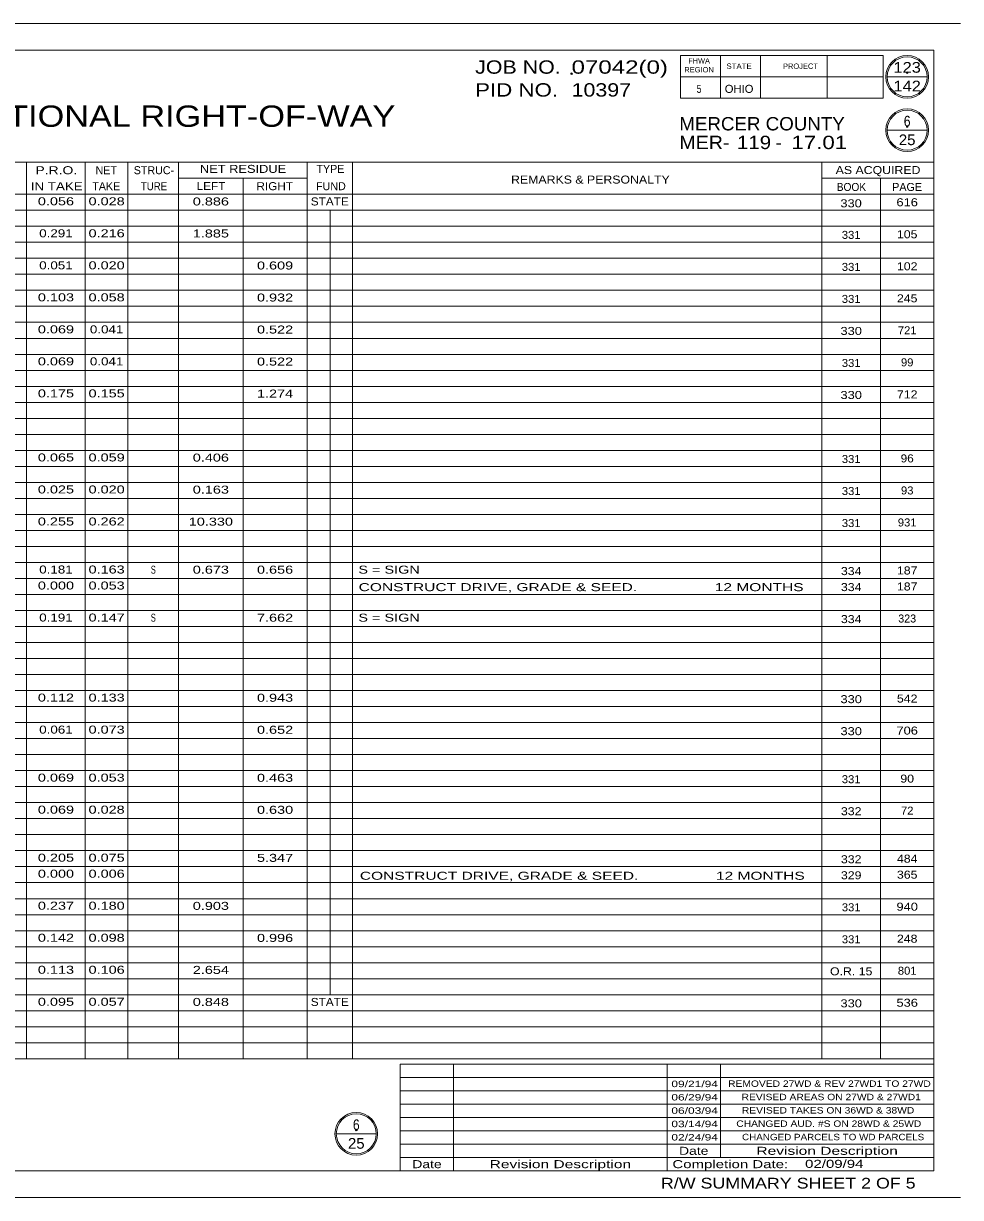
# Model space of a CAD drawing. Extents: x -1 to 34.5, y 0 to 22.
# Drawn here: x 16.94 to 34.5, y 0 to 22 of the extents above; entities that cross this region are included whole.
import ezdxf
from ezdxf.enums import TextEntityAlignment as Align

# ---------------------------------------------------------------- set-up
doc = ezdxf.new("R2010")
doc.units = 0
doc.header["$LTSCALE"] = 0.06
doc.header["$PDMODE"] = 32
doc.header["$PDSIZE"] = 0.03
doc.layers.add('1', color=7, linetype='Continuous', lineweight=13)

msp = doc.modelspace()

# ---------------------------------------------------------------- linework, layer by layer
at = {"layer": '1'}
for p, q in [((-1, 22), (34.5, 22)), ((0.5, 21.5), (34, 21.5)), ((30, 21.4), (30, 20.6)), ((30.75, 21.4), (30.75, 20.6)), ((32.002, 21.4), (32.002, 20.6)), ((29.25, 21), (33.05, 21)), ((33.125, 21), (33.875, 21)), ((33.125, 20.00258), (33.875, 20.00258)), ((0.5, 19.4), (34, 19.4)), ((16.99617, 2.6), (16.99617, 19.4)), ((18.09617, 2.6), (18.09617, 19.4)), ((18.89617, 2.6), (18.89617, 19.4)), ((19.84617, 2.6), (19.84617, 19.4)), ((22.253, 2.6), (22.253, 19.4)), ((23.103, 2.6), (23.103, 19.4)), ((31.90092, 2.6), (31.90092, 19.4)), ((19.853, 19.1), (22.253, 19.1)), ((21.053, 2.6), (21.053, 19.1)), ((31.90092, 19.1), (34, 19.1)), ((33.00092, 2.6), (33.00092, 19.1)), ((0.5, 18.8), (34, 18.8)), ((0.5, 18.5), (34, 18.5)), ((22.68783, 18.50225), (22.68783, 3.8)), ((0.5, 18.2), (34, 18.2)), ((0.5, 17.9), (34, 17.9)), ((0.5, 17.6), (34, 17.6)), ((0.5, 17.3), (34, 17.3)), ((0.5, 17), (34, 17)), ((0.5, 16.7), (34, 16.7)), ((0.5, 16.4), (34, 16.4)), ((0.5, 16.1), (34, 16.1)), ((0.5, 15.8), (34, 15.8)), ((0.5, 15.5), (34, 15.5)), ((0.5, 15.2), (34, 15.2)), ((0.5, 14.9), (34, 14.9)), ((0.5, 14.6), (34, 14.6)), ((0.5, 14.3), (34, 14.3)), ((0.5, 14), (34, 14)), ((0.5, 13.7), (34, 13.7)), ((0.5, 13.4), (34, 13.4)), ((0.5, 13.1), (34, 13.1)), ((0.5, 12.8), (34, 12.8)), ((0.5, 12.5), (34, 12.5)), ((0.5, 12.2), (34, 12.2)), ((0.5, 11.9), (34, 11.9)), ((0.5, 11.6), (34, 11.6)), ((0.5, 11.3), (34, 11.3)), ((0.5, 11), (34, 11)), ((0.5, 10.7), (34, 10.7)), ((0.5, 10.4), (34, 10.4)), ((0.5, 10.1), (34, 10.1)), ((0.5, 9.8), (34, 9.8)), ((0.5, 9.5), (34, 9.5)), ((0.5, 9.2), (34, 9.2)), ((0.5, 8.9), (34, 8.9)), ((0.5, 8.6), (34, 8.6)), ((0.5, 8.3), (34, 8.3)), ((0.5, 8), (34, 8)), ((0.5, 7.7), (34, 7.7)), ((0.5, 7.4), (34, 7.4)), ((0.5, 7.1), (34, 7.1)), ((0.5, 6.8), (34, 6.8)), ((0.5, 6.5), (34, 6.5)), ((0.5, 6.2), (34, 6.2)), ((0.5, 5.9), (34, 5.9)), ((0.5, 5.6), (34, 5.6)), ((0.5, 5.3), (34, 5.3)), ((0.5, 5), (34, 5)), ((0.5, 4.7), (34, 4.7)), ((0.5, 4.4), (34, 4.4)), ((0.5, 4.1), (34, 4.1)), ((0.5, 3.8), (34, 3.8)), ((0.5, 3.5), (34, 3.5)), ((0.5, 3.2), (34, 3.2)), ((0.5, 2.9), (34, 2.9)), ((0.5, 2.6), (34, 2.6)), ((34, 2.5), (24, 2.5)), ((24, 2.5), (24, 0.5)), ((25, 2.5), (25, 0.5)), ((29, 2.5), (29, 0.5)), ((30, 2.5), (30, 0.75)), ((34, 2.25), (24, 2.25)), ((34, 2), (24, 2)), ((34, 1.75), (24, 1.75)), ((34, 1.5), (24, 1.5)), ((22.80008, 1.1965), (23.55008, 1.1965)), ((34, 1.25), (24, 1.25)), ((34, 1), (24, 1)), ((34, 0.75), (24, 0.75)), ((-1, 0), (34.5, 0))]:
    msp.add_line(p, q, dxfattribs=at)
msp.add_lwpolyline([(34, 21.5), (34, 0.5), (0.5, 0.5)], dxfattribs=at)
msp.add_lwpolyline([(29.25, 20.6), (33.05, 20.6), (33.05, 21.4), (29.25, 21.4)], close=True, dxfattribs=at)
for centre, radius in [((33.5, 21), 0.4), ((33.5, 21), 0.375), ((33.5, 20), 0.4), ((33.5, 20), 0.375), ((23.17506, 1.19392), 0.4), ((23.17506, 1.19392), 0.375)]:
    msp.add_circle(centre, radius, dxfattribs=at)
for p in [(27.21, 21.05892), (33.5, 21.07758), (33.5, 20.07), (23.17508, 1.26392)]:
    msp.add_point(p, dxfattribs=at)

# ---------------------------------------------------------------- texts
for s, height, width, p in [('FHWA', 0.1, 0.95, (29.60004, 21.25)), ('REGION', 0.1, 1.05, (29.6, 21.08333)), ('STATE', 0.1, 1.1, (30.35, 21.15)), ('PROJECT', 0.1, 1.05, (31.50004, 21.15)), ('123', 0.2, 1.15, (33.5, 21.07758)), ('142', 0.2, 1.15, (33.5, 20.72758)), ('5', 0.15, 0.8, (29.6, 20.7)), ('OHIO', 0.15, 1.05, (30.35004, 20.7)), ('SUMMARY OF ADDITIONAL RIGHT-OF-WAY', 0.4, 1.2, (17.2385, 20.06342)), ('6', 0.2, 0.85, (33.49996, 20.07)), ('119', 0.25, 1.15, (30.62958, 19.64625)), ('25', 0.2, 1.05, (33.49996, 19.72)), ('P.R.O.', 0.15, 1.3, (17.55308, 19.175)), ('NET RESIDUE', 0.15, 1.2, (21.05304, 19.2)), ('REMARKS & PERSONALTY', 0.15, 1.15, (27.56296, 19)), ('AS ACQUIRED', 0.15, 1.15, (32.95442, 19.17858)), ('IN TAKE', 0.15, 1.25, (17.56058, 18.875)), ('LEFT', 0.15, 1.1, (20.45296, 18.87867)), ('RIGHT', 0.15, 1.1, (21.64696, 18.87642)), ('BOOK', 0.15, 0.95, (32.45529, 18.86167)), ('0.056', 0.15, 1.35, (17.54621, 18.59317)), ('0.028', 0.15, 1.35, (18.49612, 18.59317)), ('0.886', 0.15, 1.35, (20.44971, 18.59)), ('STATE', 0.15, 1.1, (22.678, 18.59)), ('330', 0.15, 1.2, (32.449, 18.55533)), ('616', 0.15, 1.2, (33.50046, 18.575)), ('0.291', 0.15, 1.25, (17.54617, 17.99317)), ('0.216', 0.15, 1.35, (18.49621, 17.99317)), ('1.885', 0.15, 1.35, (20.44963, 17.99)), ('331', 0.15, 1.05, (32.45096, 17.96367)), ('105', 0.15, 1.15, (33.50046, 17.975)), ('0.051', 0.15, 1.25, (17.54617, 17.39317)), ('0.020', 0.15, 1.35, (18.49621, 17.39317)), ('0.609', 0.15, 1.35, (21.65296, 17.39)), ('331', 0.15, 1.05, (32.45096, 17.36367)), ('102', 0.15, 1.15, (33.50054, 17.375)), ('0.103', 0.15, 1.35, (17.54612, 16.79317)), ('0.058', 0.15, 1.35, (18.49612, 16.79317)), ('0.932', 0.15, 1.35, (21.65296, 16.79)), ('331', 0.15, 1.05, (32.45096, 16.76367)), ('245', 0.15, 1.15, (33.50046, 16.775)), ('0.069', 0.15, 1.35, (17.54612, 16.19317)), ('0.041', 0.15, 1.25, (18.49617, 16.19317)), ('0.522', 0.15, 1.35, (21.65296, 16.19)), ('330', 0.15, 1.2, (32.45092, 16.16367)), ('721', 0.15, 1.05, (33.50054, 16.175)), ('0.069', 0.15, 1.35, (17.54612, 15.59317)), ('0.041', 0.15, 1.25, (18.49617, 15.59317)), ('0.522', 0.15, 1.35, (21.65296, 15.59)), ('331', 0.15, 1.05, (32.45096, 15.56367)), ('99', 0.15, 1.05, (33.50046, 15.575)), ('0.175', 0.15, 1.35, (17.54612, 14.99317)), ('0.155', 0.15, 1.35, (18.49612, 14.99317)), ('1.274', 0.15, 1.35, (21.65296, 14.99)), ('330', 0.15, 1.2, (32.45092, 14.96367)), ('712', 0.15, 1.15, (33.50054, 14.975)), ('0.065', 0.15, 1.35, (17.54612, 13.79317)), ('0.059', 0.15, 1.35, (18.49612, 13.79317)), ('0.406', 0.15, 1.35, (20.44971, 13.79)), ('331', 0.15, 1.05, (32.45096, 13.76367)), ('96', 0.15, 1.1, (33.5005, 13.775)), ('0.025', 0.15, 1.35, (17.54612, 13.19317)), ('0.020', 0.15, 1.35, (18.49621, 13.19317)), ('0.163', 0.15, 1.35, (20.44963, 13.19)), ('331', 0.15, 1.05, (32.45096, 13.16367)), ('93', 0.15, 1.05, (33.5005, 13.175)), ('0.255', 0.15, 1.35, (17.54612, 12.59317)), ('0.262', 0.15, 1.35, (18.49612, 12.59317)), ('10.330', 0.15, 1.35, (20.44963, 12.59)), ('331', 0.15, 1.05, (32.45096, 12.56367)), ('931', 0.15, 1.05, (33.50054, 12.575)), ('0.181', 0.15, 1.25, (17.54617, 11.69317)), ('0.163', 0.15, 1.35, (18.49612, 11.69317)), ('S', 0.15, 0.7, (19.37112, 11.69)), ('0.673', 0.15, 1.35, (20.44963, 11.69)), ('0.656', 0.15, 1.35, (21.65304, 11.69)), ('334', 0.15, 1.15, (32.45087, 11.66367)), ('187', 0.15, 1.15, (33.5005, 11.675)), ('0.000', 0.15, 1.35, (17.54621, 11.39317)), ('0.053', 0.15, 1.35, (18.49612, 11.39317)), ('334', 0.15, 1.15, (32.45087, 11.36367)), ('187', 0.15, 1.15, (33.5005, 11.375)), ('0.191', 0.15, 1.25, (17.54617, 10.79317)), ('0.147', 0.15, 1.35, (18.49612, 10.79317)), ('S', 0.15, 0.7, (19.37112, 10.79)), ('7.662', 0.15, 1.35, (21.65296, 10.79)), ('334', 0.15, 1.15, (32.45087, 10.76367)), ('0.112', 0.15, 1.35, (17.54612, 9.29317)), ('0.133', 0.15, 1.35, (18.49612, 9.29317)), ('0.943', 0.15, 1.35, (21.65296, 9.29)), ('330', 0.15, 1.2, (32.45092, 9.26367)), ('542', 0.15, 1.15, (33.50054, 9.275)), ('0.061', 0.15, 1.25, (17.54617, 8.69317)), ('0.073', 0.15, 1.35, (18.49612, 8.69317)), ('0.652', 0.15, 1.35, (21.65296, 8.69)), ('330', 0.15, 1.2, (32.45092, 8.66367)), ('706', 0.15, 1.2, (33.50046, 8.675)), ('0.069', 0.15, 1.35, (17.54612, 7.79317)), ('0.053', 0.15, 1.35, (18.49612, 7.79317)), ('0.463', 0.15, 1.35, (21.65296, 7.79)), ('90', 0.15, 1.15, (33.50046, 7.775)), ('331', 0.15, 1.05, (32.45096, 7.76367)), ('0.069', 0.15, 1.35, (17.54612, 7.19317)), ('0.028', 0.15, 1.35, (18.49612, 7.19317)), ('0.630', 0.15, 1.35, (21.65304, 7.19)), ('332', 0.15, 1.15, (32.45096, 7.16367)), ('72', 0.15, 1.05, (33.5005, 7.175)), ('0.205', 0.15, 1.35, (17.54612, 6.29317)), ('0.075', 0.15, 1.35, (18.49612, 6.29317)), ('5.347', 0.15, 1.35, (21.65296, 6.29)), ('332', 0.15, 1.15, (32.45096, 6.26367)), ('484', 0.15, 1.15, (33.50046, 6.275)), ('0.000', 0.15, 1.35, (17.54621, 5.99317)), ('0.006', 0.15, 1.35, (18.49621, 5.99317)), ('329', 0.15, 1.15, (32.45092, 5.96367)), ('365', 0.15, 1.15, (33.50046, 5.975)), ('0.237', 0.15, 1.35, (17.54612, 5.39317)), ('0.180', 0.15, 1.35, (18.49621, 5.39317)), ('0.903', 0.15, 1.35, (20.44963, 5.39)), ('331', 0.15, 1.05, (32.45096, 5.36367)), ('940', 0.15, 1.2, (33.5005, 5.375)), ('0.142', 0.15, 1.35, (17.54612, 4.79317)), ('0.098', 0.15, 1.35, (18.49612, 4.79317)), ('0.996', 0.15, 1.35, (21.65304, 4.79)), ('331', 0.15, 1.05, (32.45096, 4.76367)), ('248', 0.15, 1.15, (33.5005, 4.775)), ('0.113', 0.15, 1.35, (17.54612, 4.19317)), ('0.106', 0.15, 1.35, (18.49621, 4.19317)), ('2.654', 0.15, 1.35, (20.44963, 4.19)), ('O.R. 15', 0.15, 1.15, (32.45087, 4.16367)), ('801', 0.15, 1.05, (33.50054, 4.175)), ('0.095', 0.15, 1.35, (17.54612, 3.59317)), ('0.057', 0.15, 1.35, (18.49612, 3.59317)), ('0.848', 0.15, 1.35, (20.44963, 3.59)), ('STATE', 0.15, 1.1, (22.678, 3.59)), ('330', 0.15, 1.2, (32.45092, 3.56367)), ('536', 0.15, 1.2, (33.50046, 3.575)), ('6', 0.2, 0.85, (23.17504, 1.26392)), ('25', 0.2, 1.05, (23.17504, 0.91392)), ('Date', 0.15, 1.3, (29.5, 0.8)), ('Revision Description', 0.15, 1.45, (32, 0.8)), ('Date', 0.15, 1.3, (24.5, 0.55)), ('Revision Description', 0.15, 1.45, (27, 0.55))]:
    msp.add_text(s, height=height, dxfattribs=dict(at, width=width)).set_placement(p, align=Align.CENTER)
for s, height, width, p in [('JOB NO.', 0.25, 1.2, (25.40233, 21.05892)), ('07042(0)', 0.25, 1.35, (27.21, 21.05892)), ('PID NO.', 0.25, 1.25, (25.40233, 20.63033)), ('10397', 0.25, 1.2, (27.21, 20.63033)), ('MERCER COUNTY', 0.25, 1.05, (29.22958, 19.99625)), ('MER-', 0.25, 1.1, (29.22958, 19.64625)), ('17.01', 0.25, 1.25, (31.32958, 19.64625)), ('-', 0.25, 1.1, (31.02958, 19.64625)), ('TURE', 0.15, 0.9, (19.13825, 18.87483)), ('S = SIGN', 0.15, 1.35, (23.21425, 11.69067)), ('CONSTRUCT DRIVE, GRADE & SEED.                  12 MONTHS', 0.15, 1.45, (23.21942, 11.36258)), ('S = SIGN', 0.15, 1.35, (23.21425, 10.79067)), ('CONSTRUCT DRIVE, GRADE & SEED.                  12 MONTHS', 0.15, 1.45, (23.24192, 5.9545)), ('09/21/94', 0.12, 1.4, (29.08008, 2.06833)), ('REMOVED 27WD & REV 27WD1 TO 27WD', 0.12, 1.2, (30.144, 2.07392)), ('06/29/94', 0.12, 1.4, (29.08008, 1.81833)), ('REVISED AREAS ON 27WD & 27WD1', 0.12, 1.2, (30.39667, 1.82392)), ('06/03/94', 0.12, 1.4, (29.08008, 1.56833)), ('REVISED TAKES ON 36WD & 38WD', 0.12, 1.2, (30.40192, 1.57392)), ('03/14/94', 0.12, 1.4, (29.08008, 1.31833)), ('CHANGED AUD. #S ON 28WD & 25WD', 0.12, 1.2, (30.29725, 1.32392)), ('02/24/94', 0.12, 1.4, (29.08008, 1.06833)), ('CHANGED PARCELS TO WD PARCELS', 0.12, 1.15, (30.40467, 1.07392)), ('Completion Date:', 0.15, 1.4, (29.1, 0.55)), ('02/09/94', 0.15, 1.4, (31.58708, 0.55625))]:
    msp.add_text(s, height=height, dxfattribs=dict(at, width=width)).set_placement(p)
for s, p in [('NET', (18.48912, 19.175)), ('STRUC-', (19.38237, 19.17558)), ('TYPE', (22.691, 19.2)), ('TAKE', (18.48908, 18.875)), ('FUND', (22.69962, 18.87642)), ('PAGE', (33.49883, 18.86167)), ('323', (33.5005, 10.775))]:
    msp.add_text(s, height=0.15, dxfattribs=at).set_placement(p, align=Align.CENTER)
at = {"layer": '1', "width": 1.25}
msp.add_text('R/W SUMMARY SHEET 2 OF 5', height=0.2, dxfattribs=at).set_placement((33.65833, 0.16892), align=Align.RIGHT)

doc.saveas('drawing.dxf')
